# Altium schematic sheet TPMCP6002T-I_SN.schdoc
size 127 x 101 mm
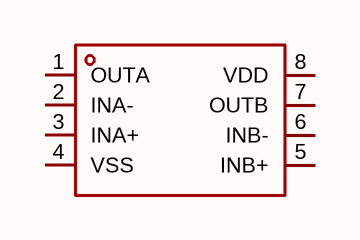
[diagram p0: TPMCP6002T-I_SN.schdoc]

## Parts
U?  tpmcp6002t-i/sn  [SOP-8_L4.9-W3.9-P1.27-LS6.0-BL]  (value not drawn)

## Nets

Not connected (* = marked no-connect by the designer): U? 1(OUTA) 2(INA-) 3(INA+) 4(VSS) 5(INB+) 6(INB-) 7(OUTB) 8(VDD)

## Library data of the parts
U? = tpmcp6002t-i/sn: 放大器数:2;轨到轨:轨到轨输入,轨到轨输出;增益带宽积(GBW):1MHz;输入失调电压(Vos):5mV;压摆率(SR):600V/ms;输入偏置电流(Ib):10pA;; Manufacturer: TECH PUBLIC(台舟); AddInBom: yes; ModelId: 75c24a7891ee4dd6bdac16a7163ff87e; ModelName: SOP-8_L4.9-W3.9-P1.27-LS6.0-BL-1; ModelTransform: 192.913,236.22,0,0,0,0,-0.393,2.749,0; Number of Channels: 2; Maximum Power Supply Range (Vdd-Vss): 7V; Gain Bandwidth Product: 1MHz; Vos - Input Offset Voltage: 5mV; Input Offset Voltage Drift(Vos TC): 2uV/℃; Ib - Input Bias Current: 10pA; Input Voltage Noise Density: 20nV/√Hz@10kHz; Common Mode Rejection Ratio(CMRR): 80dB; Quiescent Current: 55uA; Output Current: 20mA; Single supply: 1.8V~5.5V; Dual Supply: -2.75V~-900mV；900mV~2.75V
